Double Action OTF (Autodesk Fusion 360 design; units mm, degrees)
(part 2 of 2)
sketch "Sketch2" plane through (0, 0, 12.4) normal (0, 0, 1) x axis (-1, 0, 0)
  line L1 (-29, -98) -> (-29, -2)
  line L2 (-2, -99) -> (-28, -99)
  line L3 (-1, -2) -> (-1, -98)
  line L4 (-28, -1) -> (-2, -1)
  line L5 (-14.25, -94) -> (-4.25, -94)
  line L6 (-14.25, -81.0403) -> (-14.25, -94)
  line L7 (-4.25, -77) -> (-14.25, -81.0403)
  line L8 (-4.25, -94) -> (-4.25, -77)
  line L9 (-4.25, -67) -> (-4.25, -75.3822)
  line L10 (-14.25, -67) -> (-4.25, -67)
  line L11 (-14.25, -79.4225) -> (-14.25, -67)
  line L12 (-4.25, -75.3822) -> (-14.25, -79.4225)
  line L13 (-15.75, -83.4225) -> (-15.75, -67)
  line L14 (-25.75, -79.3822) -> (-15.75, -83.4225)
  line L15 (-25.75, -67) -> (-25.75, -79.3822)
  line L16 (-15.75, -67) -> (-25.75, -67)
  line L17 (-15.75, -94) -> (-15.75, -85.0403)
  line L18 (-25.75, -94) -> (-15.75, -94)
  line L19 (-25.75, -81) -> (-25.75, -94)
  line L20 (-15.75, -85.0403) -> (-25.75, -81)
  arc A1 centre (-28, -98) radius 1 clockwise from (-28, -99) to (-29, -98)
  arc A2 centre (-2, -98) radius 1 clockwise from (-1, -98) to (-2, -99)
  arc A3 centre (-2, -2) radius 1 clockwise from (-2, -1) to (-1, -2)
  arc A4 centre (-28, -2) radius 1 clockwise from (-29, -2) to (-28, -1)
  point P14 (-4.25, -94)
  point P17 (-4.25, -77)
  point P28 (-25.75, -94)
  point P29 (-25.75, -81)
  horizontal L5
  perpendicular L5 L6
  perpendicular L5 L9
  perpendicular L9 L10
  perpendicular L10 L11
  parallel L9 L13
  parallel L13 L15
  perpendicular L16 L17
  perpendicular L17 L18
  perpendicular L18 L19
  vertical L8
  collinear L6 L11
  collinear L13 L17
  collinear L15 L19
  collinear L5 L18
  collinear L10 L16
  parallel L7 L12
  parallel L14 L20
  collinear L8 L9
  dimension "d395" distance L3 L8 = 3.25
  dimension "d396" distance L6 L8 = 10
  dimension "d397" distance L6 L17 = 1.5
  dimension "d398" distance L7 L12 = 1.5
  dimension "d399" distance L14 L20 = 1.5
  dimension "d400" distance L17 L19 = 10
  dimension "d401" distance L5 L10 = 27
  dimension "d402" distance L1 L19 = 3.25
  dimension "d403" distance L2 L5 = 5
  dimension "d404" distance P14 P17 = 17
  dimension "d405" distance P28 P29 = 13
  dimension "d406" angle L17 L20 = 112
  dimension "d407" angle L6 L7 = 112
extrude "Extrude1" new body sketch "Sketch2" profile of L5 L6 L7 L8 L9 L10 L11 L12 L13 L14 L15 L16 L17 L18 L19 L20 against normal blind 1
mirror "Mirror1" mirrorStitchTolerance 0.1
move "Move1"
combine "Combine2"
combine "Combine3"
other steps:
chamfer "Chamfer1" distance 1 distance 0.5
chamfer "Chamfer1" distance 0.5 distance 1
fillet "Fillet2" radius 2
chamfer "Chamfer2" distance 1 distance 0.5
create_component "CreateComponent1"
create_component "CreateComponent3"
create_component "CreateComponent4"
create_component "CreateComponent5"
create_component "CreateComponent6"
remove_body "RemoveBody1"
create_component "CreateComponent7"
create_component "CreateComponent8"
create_component "CreateComponent9"
create_component "CreateComponent10"
create_component "CreateComponent11"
